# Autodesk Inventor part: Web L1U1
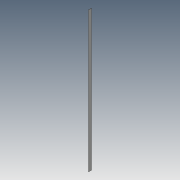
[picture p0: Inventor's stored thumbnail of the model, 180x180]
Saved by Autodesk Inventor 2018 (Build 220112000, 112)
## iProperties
Created: 2018-02
Part Number: Web L1U1
Material: Steel, Mild
Document SubType Name: Modeling
Designer: STK
Density: 7.85 g/cm^3
Appearance: Light Gray
Mass: 179451 g
Surface Area: 38372.5 cm^2
Volume: 22860 cm^3
Author: STK
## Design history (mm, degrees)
sketch "Sketch1"
  geometry: L1 (6.35, 98.425)-(-6.35, 98.425); L2 (-6.35, 98.425)-(-6.35, -98.425); L3 (-6.35, -98.425)-(6.35, -98.425); L4 (6.35, -98.425)-(6.35, 98.425); L5 (6.35, 98.425)-(-6.35, -98.425); L6 (-6.35, 98.425)-(6.35, -98.425); 1 further point
  constraints: 12 end point, 2 midpoint, 2 parallel, 1 horizontal, 1 perpendicular
  dimensions: "d0" = 12.7 distance of L3.end L2.end; "d1" = 196.85 distance of L2.end L1.end
extrude "Extrusion1" new body sketch "Sketch1" stored distance "d2" = 9144; taper "d3" = 0 deg
body "Solid1"
